// Mitsubishi GX Works2 project: 15.计时程序   PLC: FX3U/FX3UC

PROGRAM MAIN
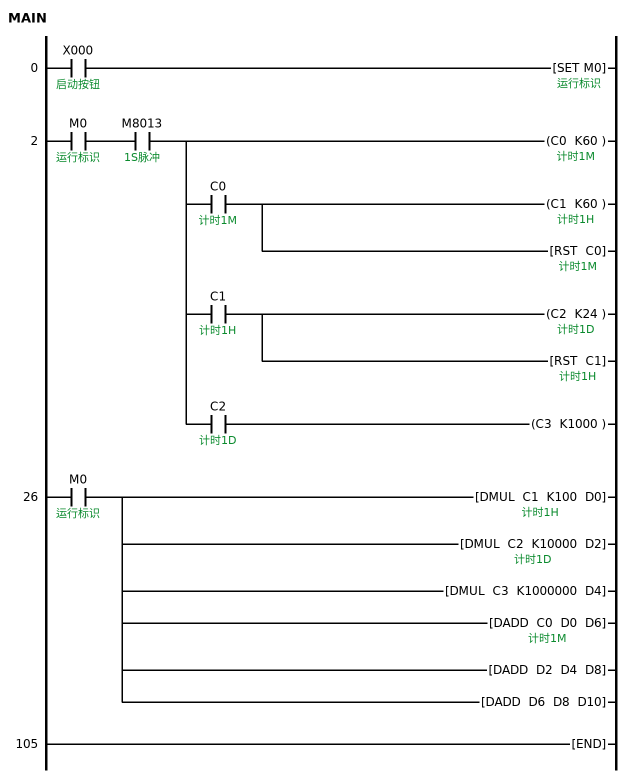
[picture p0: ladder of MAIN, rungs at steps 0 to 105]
0     LD      X000  ; 启动按钮
      SET     M0  ; 运行标识
2     LD      M0  ; 运行标识
      AND     M8013  ; 1S脉冲
      OUT     C0 K60  ; 计时1M
      MPS
      AND     C0  ; 计时1M
      OUT     C1 K60  ; 计时1H
      RST     C0  ; 计时1M
      MRD
      AND     C1  ; 计时1H
      OUT     C2 K24  ; 计时1D
      RST     C1  ; 计时1H
      MPP
      AND     C2  ; 计时1D
      OUT     C3 K1000
26    LD      M0  ; 运行标识
      DMUL    C1 K100 D0
        [note] 把分钟数*100
      DMUL    C2 K10000 D2
        [note] 把小时数*1W
      DMUL    C3 K1000000 D4
        [note] 把天数*100W
      DADD    C0 D0 D6
        [note] 秒数+分钟数寄存到D6
      DADD    D2 D4 D8
        [note] 小时数+天钟数寄存到D8
      DADD    D6 D8 D10
        [note] D10：天；小时；分；秒的格式
105   END
END_PROGRAM
